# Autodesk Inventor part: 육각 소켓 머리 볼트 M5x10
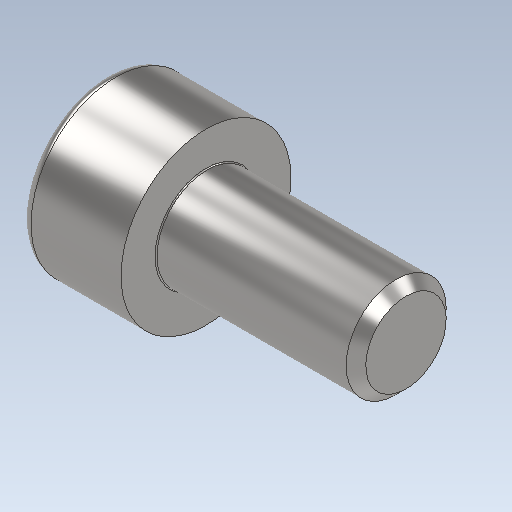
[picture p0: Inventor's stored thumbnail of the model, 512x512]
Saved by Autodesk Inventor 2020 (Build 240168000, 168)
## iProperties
Created: 2024-09
Part Number: 육각 소켓 머리 볼트 M5x10
Material: 강철, 연강
Description: 6각머리 태핑 나사
Document SubType Name: Modeling
Designer: oem
Density: 7.85 g/cm^3
Appearance: 기본값
Author: jhkim
Sending System: Autodesk Inventor 2025
Preprocessor: ST-DEVELOPER v20
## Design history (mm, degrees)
feature "Solid1"
node "솔리드1"
